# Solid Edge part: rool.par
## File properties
Author: Blackblade
Template: Normal.par
Last saved by: Blackblade
Revision: 9
Application: Solid Edge
Accuracy: 0.990
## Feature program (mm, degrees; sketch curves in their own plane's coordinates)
sketch for "unnamed RevolvedProtrusion 1" plane through (0, 0, 0) normal (1, 0, 0) x-axis (0, 1, 0)
  circle centre (0, 10) radius 1
revolve "unnamed RevolvedProtrusion 1" add full turn 360 deg
sketch for "unnamed Protrusion 1" plane through (0, 0, 0) normal (0, -1, 0) x-axis (1, 0, 0)
  circle centre (0, 0) radius 2.0133
extrude "unnamed Protrusion 1" add finite 2 symmetric
sketch for "unnamed Protrusion 2" plane through (0, 0, 0) normal (1, 0, 0) x-axis (0, 1, 0)
  line (-0.5, 0.5) -> (-0.5, -0.5)
  line (-0.5, -0.5) -> (0.5, -0.5)
  line (0.5, -0.5) -> (0.5, 0.5)
  line (0.5, 0.5) -> (-0.5, 0.5)
extrude "unnamed Protrusion 2" add to key point along +normal
pattern "unnamed Pattern 1" of "unnamed Protrusion 2"
pattern "unnamed Pattern 2"
sketch for "unnamed RevolvedCutout 1" plane through (0, 0, 0) normal (1, 0, 0) x-axis (0, 1, 0)
revolve "unnamed RevolvedCutout 1" cut finite 360 deg
sketch for "ExtrudedProtrusion_7" plane through (0, 1, 0) normal (0, 1, 0) x-axis (0, 0, -1)
  circle centre (0, 0) radius 1.5
extrude "ExtrudedProtrusion_7" add finite 3 along +normal
lofted protrusion "unnamed LoftedProtrusion 1"
sketch for "ExtrudedProtrusion_8" plane through (1.1472, 5.6383, 0) normal (0.573576, 0.819152, 0) x-axis (0, 0, 1)
extrude "ExtrudedProtrusion_8" add finite 5 along +normal
chamfer "Chamfer_1" setback 1
sketch for "ExtrudedProtrusion_9" plane through (4.015, 9.7341, 0) normal (0.573576, 0.819152, 0) x-axis (0, 0, -1)
extrude "ExtrudedProtrusion_9" add finite 21.3 along +normal
sketch used by "ExtrudedProtrusion_10" plane through (1.2049, 9.3831, 0) normal (-0.819152, 0.573576, 0) x-axis (0, 0, 1)
  line (-1.3555, -2.1006) -> (-1.3555, -1.0729)
  line (-1.3555, -1.0729) -> (1.3555, -1.0729)
  line (1.3555, -1.0729) -> (1.3555, -2.1006)
  line (1.3555, -2.1006) -> (-1.3555, -2.1006)
extrude "ExtrudedProtrusion_10" add finite 4.72 along +normal
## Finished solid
Body 1: solid body, 30 faces, 67 edges, 40 vertices.
  Faces by surface: plane 24, cylinder 3, cone 1, spline 1, torus 1
  Edges by curve: line 34, circle 24, intersection 8, curve on surface 1
Bounding box of the edges (mm; curved faces can reach further): 27.414 x 29.616 x 18.268, from (-9.134, -1, -9.134) to (18.2801, 28.6159, 9.134).
Cylindrical faces by radius (mm): R1.5 x1, R2.0133 x1, R2.5 x1
Conical faces (half-angle, radius in mm at the cone's reference point): 45 deg R1.5 x1
Toroidal faces (ring radius, tube radius in mm): R10 r1 x1
Planar faces by outward normal: +x 2, +y 5, +z 3, -x 2, -y 5, -z 3, oblique 4
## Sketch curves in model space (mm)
circle centre (1.1472, 5.6383, 0) radius 1.5
line (0.5895, 8.5042, -1.3555) -> (0.5895, 8.5042, 1.3555)
line (0.5895, 8.5042, 1.3555) -> (0, 7.6623, 1.3555)
line (0, 7.6623, 1.3555) -> (0, 7.6623, -1.3555)
line (0, 7.6623, -1.3555) -> (0.5895, 8.5042, -1.3555)
line (0, -2.2786, 0) -> (0, -1.532, 0)
arc centre (0, 0, 10) radius 1 from (0, -1, 10) through (0, 0.0296, 10.9996) to (0, 1, 10)
line (0, 0.5, -0.5) -> (0, 0.5, 0.5)
line (0, 0.5, 0.5) -> (0, -0.5, 0.5)
line (0, -0.5, 0.5) -> (0, -0.5, -0.5)
line (0, -0.5, -0.5) -> (0, 0.5, -0.5)
circle centre (0, 0, 0) radius 2.0133
circle centre (0, 0, 10) radius 1
line (0, -2.4695, 0) -> (0, 2.0205, 0)
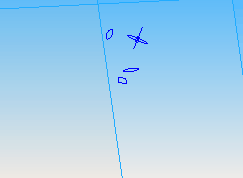
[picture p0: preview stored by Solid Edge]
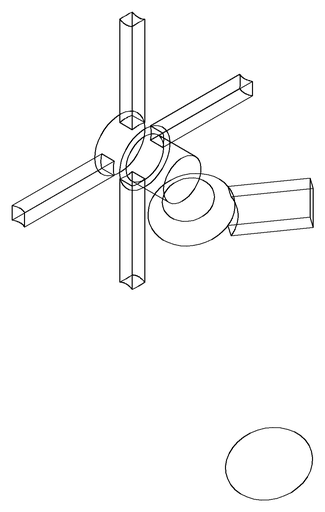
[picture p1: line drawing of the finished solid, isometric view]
